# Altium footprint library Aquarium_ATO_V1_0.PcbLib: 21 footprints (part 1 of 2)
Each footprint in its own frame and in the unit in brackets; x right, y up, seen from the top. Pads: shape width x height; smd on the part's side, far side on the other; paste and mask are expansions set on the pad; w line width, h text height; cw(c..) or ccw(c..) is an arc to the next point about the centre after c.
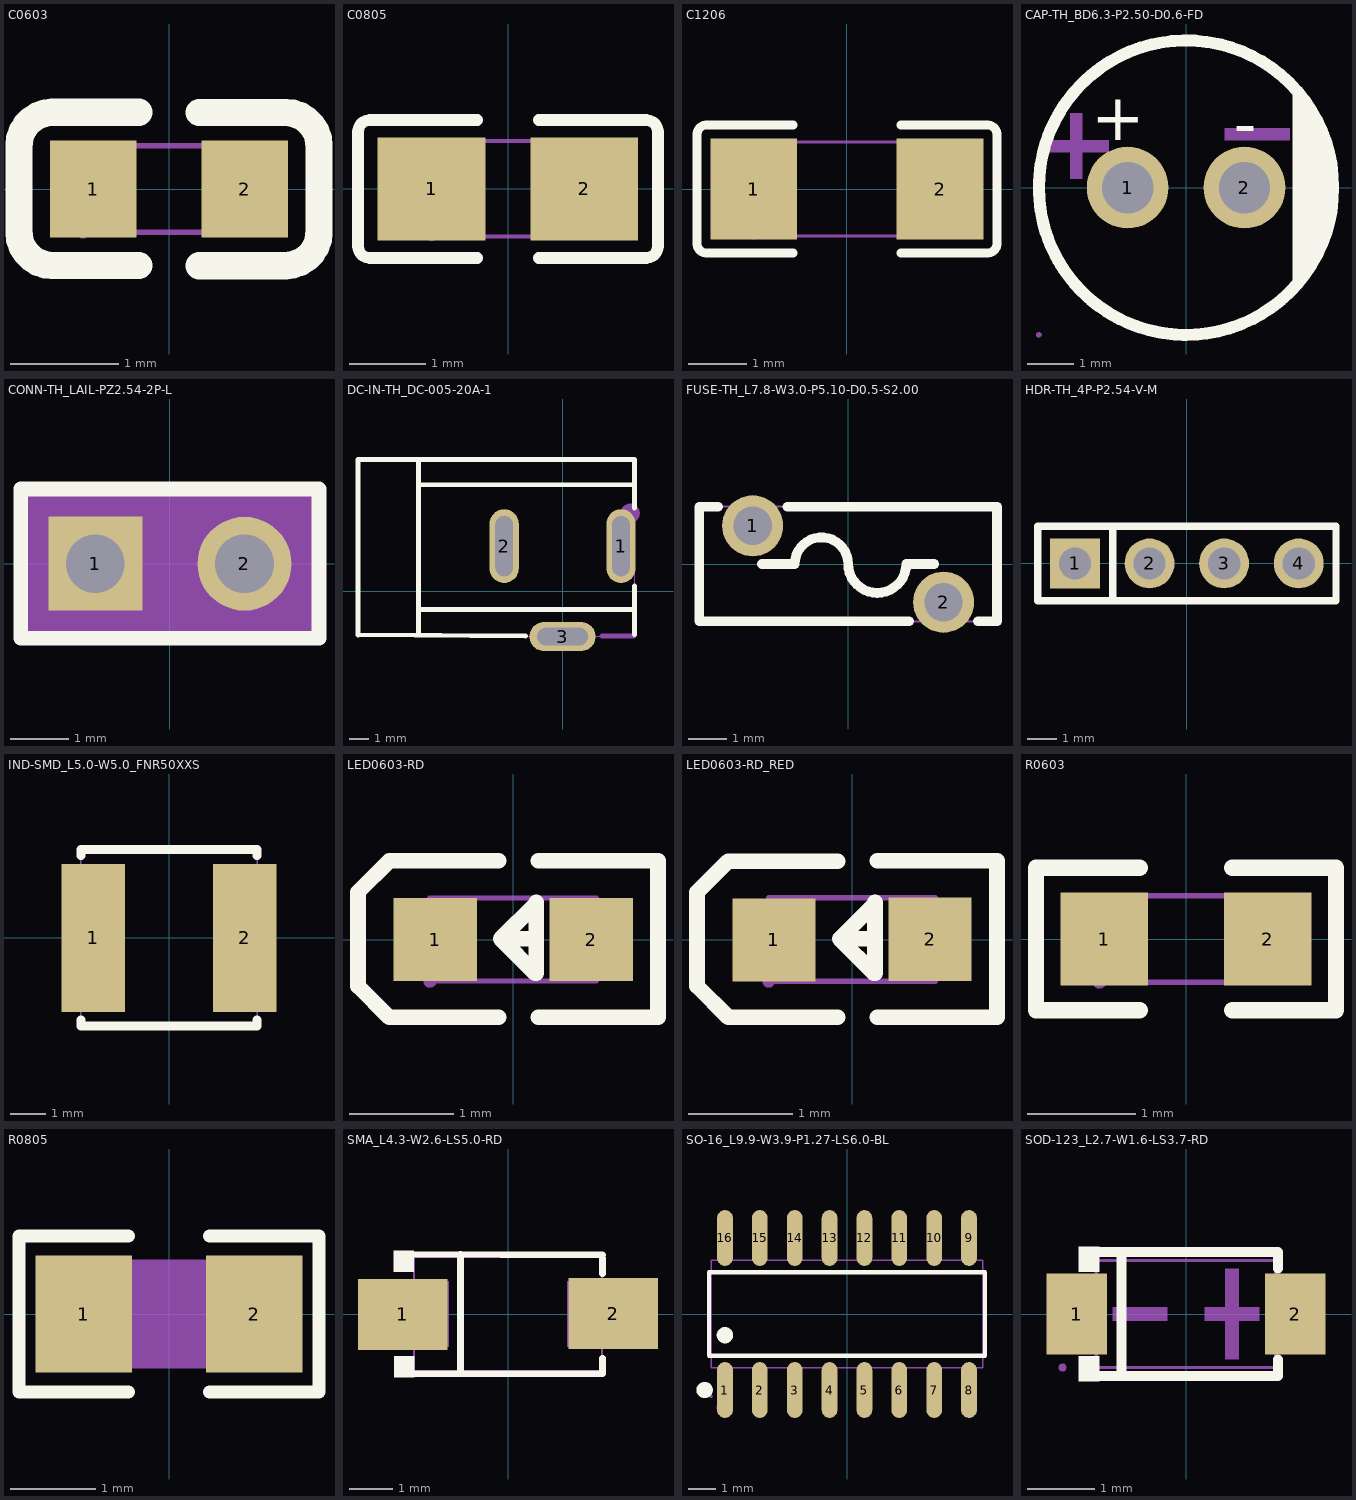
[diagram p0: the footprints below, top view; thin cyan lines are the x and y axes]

## C0603 [mil]
pads (2):
  rect 31.5x35.4 smd: 1(-27.6,0) 2(27.6,0)
Top Overlay:
  lines w10: -11,-27.9 -42.5,-27.9 -45.2,-27.6 -47.8,-26.7 -50.1,-25.3 -52.1,-23.3 -53.5,-21 -54.4,-18.5 -54.7,-15.7 -54.7,15.8 -54.4,18.5 -53.5,21 -52.1,23.4 -50.1,25.3 -47.8,26.7 -45.2,27.7 -42.5,28 -11,28 ; 11,-28 42.5,-28 45.2,-27.6 47.8,-26.7 50.1,-25.3 52.1,-23.4 53.5,-21 54.4,-18.5 54.7,-15.8 54.7,15.7 54.4,18.5 53.5,21 52.1,23.3 50.1,25.3 47.8,26.7 45.2,27.6 42.5,27.9 11,27.9
Mechanical 7:
  lines w2: -31.5,-15.7 31.5,-15.7 31.5,15.7 -31.5,15.7 -31.5,-15.7
Mechanical 8:
  region: -29.1,-15.8 -29.5,-17 -30.5,-17.9 -31.8,-18.1 -33,-17.5 -33.8,-16.4 -33.8,-15.1 -33,-14 -31.8,-13.4 -30.5,-13.6 -29.5,-14.5
Mechanical 9:
  region: 31.5,-15.7 31.5,15.7 19.7,15.7 19.7,-15.7
  region: -31.5,-15.7 -31.5,15.7 -19.7,15.7 -19.7,-15.7

## C0805 [mil]
pads (2):
  rect 55.5x53.1 smd paste-3937 mask+2: 1(-39.4,0) 2(39.3,0)
Top Overlay:
  lines w6: -15.8,-35.6 -71.3,-35.6 -73.2,-35.3 -74.9,-34.5 -76.2,-33.1 -77,-31.5 -77.3,-29.6 -77.3,29.5 -77,31.4 -76.2,33.1 -74.9,34.4 -73.2,35.2 -71.3,35.5 -15.8,35.5 ; 15.8,-35.6 71.3,-35.6 73.1,-35.3 74.8,-34.5 76.1,-33.1 77,-31.5 77.3,-29.6 77.3,29.5 77,31.4 76.1,33.1 74.8,34.4 73.1,35.2 71.3,35.5 15.8,35.5
Top Paste:
  region: -67.2,-25.2 -67.2,25.2 -65.2,27.1 -19.9,27.1 -17.9,25.2 -17.7,9 -35.5,9 -35.5,-8.7 -18.1,-8.7 -17.9,-25.2 -19.9,-27.2 -65.2,-27.2
  region: 67.1,25.2 67.1,-25.2 65.1,-27.2 19.9,-27.2 17.9,-25.2 17.7,-9.1 35.4,-9.1 35.4,8.6 18.1,8.6 17.9,25.2 19.9,27.1 65.1,27.1
Mechanical 7:
  lines w2: -39.4,-24.6 -39.4,24.6 39.3,24.6 39.3,-24.6 -39.4,-24.6
Mechanical 8:
  region: -37,-24.6 -37.4,-25.9 -38.4,-26.8 -39.7,-27 -40.9,-26.4 -41.7,-25.3 -41.7,-24 -40.9,-22.9 -39.7,-22.3 -38.4,-22.5 -37.4,-23.4
Mechanical 9:
  region: -39.4,-24.6 -39.4,24.6 -19.7,24.6 -19.7,-24.6
  region: 39.3,24.6 39.3,-24.6 19.7,-24.6 19.7,24.6

## C1206 [mil]
pads (2):
  rect 58.5x68 smd paste-3937 mask+2: 1(-62.7,0) 2(62.7,0)
Top Overlay:
  lines w6: -36.4,-43 -94.9,-43 -96.7,-42.7 -98.4,-41.9 -99.7,-40.6 -100.6,-38.9 -100.9,-37 -100.9,37 -100.6,38.8 -99.7,40.5 -98.4,41.8 -96.7,42.7 -94.9,43 -36.4,43 ; 36.5,-43 95,-43 96.8,-42.7 98.5,-41.9 99.8,-40.6 100.7,-38.9 101,-37 101,37 100.7,38.8 99.8,40.5 98.5,41.8 96.8,42.7 95,43 36.5,43
Top Paste:
  region: 33.5,-30.1 33.5,-15.5 37.5,-11.6 49.5,-11.6 53.4,-7.6 53.4,7.6 49.5,11.5 37.5,11.5 33.5,15.5 33.5,30.1 37.5,34 88,34 92,30.1 92,-30.1 88,-34 37.5,-34
  region: -33.4,-30.1 -33.4,-15.5 -37.4,-11.6 -49.4,-11.6 -53.3,-7.6 -53.3,7.6 -49.4,11.5 -37.4,11.5 -33.4,15.5 -33.4,30.1 -37.4,34 -87.9,34 -91.9,30.1 -91.9,-30.1 -87.9,-34 -37.4,-34
Mechanical 7:
  lines w2: -62.9,-31.5 -62.9,31.5 63,31.5 63,-31.5 -62.9,-31.5
Mechanical 8:
  region: -60.6,-31.5 -61,-32.8 -62,-33.7 -63.3,-33.9 -64.5,-33.3 -65.2,-32.2 -65.2,-30.9 -64.5,-29.7 -63.3,-29.2 -62,-29.4 -61,-30.2
Mechanical 9:
  region: -62.9,-31.5 -62.9,31.5 -43.3,31.5 -43.3,-31.5
  region: 63,-31.5 63,31.5 43.4,31.5 43.4,-31.5

## CAP-TH_BD6.3-P2.50-D0.6-FD [mil]
pads (2):
  round 68.9 hole 43.3 paste+0 mask+2: 1(-49.2,0) 2(49.2,0)
Top Overlay:
  drawing of 160 lines, arcs and shapes, not listed
  text "-" at 40,35 h39.4
  text "+" at -80,40 h39.4
Mechanical 6:
  region: 32.5,50 87.5,50 87.5,40 32.5,40
  region: -97.5,7.5 -97.5,62.5 -87.5,62.5 -87.5,7.5
  region: -120,40 -65,40 -65,30 -120,30
Mechanical 7:
  lines w2: -0.1,-124.1 0,-124.1 ccw(c0,-0.2) 123.9,-0.2 123.9,0.2 ccw(c0,0.2) 0,124.1 -0.1,124.1 ccw(c-0.1,0.1) -124.1,0.1 -124.1,0 ccw(c-0.1,0) -0.1,-124
Mechanical 8:
  region: -121.7,-124.1 -122.1,-125.3 -123.1,-126.2 -124.4,-126.4 -125.6,-125.8 -126.4,-124.7 -126.4,-123.4 -125.6,-122.3 -124.4,-121.7 -123.1,-121.9 -122.1,-122.8
Mechanical 9:
  region: 61,0 60.7,-2.9 59.6,-5.7 57.8,-8.1 55.5,-10 52.9,-11.2 50,-11.8 47,-11.6 44.2,-10.7 41.7,-9.1 39.7,-6.9 38.2,-4.3 37.5,-1.5 37.5,1.5 38.2,4.3 39.7,6.9 41.7,9.1 44.2,10.7 47,11.6 50,11.8 52.9,11.2 55.5,10 57.8,8.1 59.6,5.7 60.7,2.9
  region: -37.4,0 -37.8,-2.9 -38.9,-5.7 -40.6,-8.1 -42.9,-10 -45.6,-11.2 -48.5,-11.8 -51.4,-11.6 -54.2,-10.7 -56.7,-9.1 -58.8,-6.9 -60.2,-4.3 -60.9,-1.5 -60.9,1.5 -60.2,4.3 -58.8,6.9 -56.7,9.1 -54.2,10.7 -51.4,11.6 -48.5,11.8 -45.6,11.2 -42.9,10 -40.6,8.1 -38.9,5.7 -37.8,2.9

## CONN-TH_LAIL-PZ2.54-2P-L [mil]
pads (2):
  rect 63x63 hole 39.4 paste+0 mask+2: 1(-50,0)
  round 63 hole 39.4 paste+0 mask+2: 2(50,0)
Top Overlay:
  lines w10: -100,-50 100,-50 100,50 -100,50 -100,-50
Mechanical 7:
  region: -100,-49.2 -100,49.2 100,49.2 100,-49.2
Mechanical 8:
  region: -98.8,-49.2 -99.2,-50 -100,-50.4 -100.8,-50 -101.2,-49.2 -100.8,-48.4 -100,-48 -99.2,-48.4
Mechanical 9:
  region: 37.4,12.6 62.6,12.6 62.6,-12.6 37.4,-12.6
  region: -62.6,12.6 -37.4,12.6 -37.4,-12.6 -62.6,-12.6

## DC-IN-TH_DC-005-20A-1 [mil]
pads (3):
  oval 59.1x149.6 hole 35.4 slot 122.1 at 90 deg: 1(118.2,91.5) 2(-118.1,91.5)
  oval 133.9x59.1 hole 35.4 slot 102.4 at 0 deg: 3(0,-91.5)
Top Overlay:
  lines w10: -413.9,-87.9 -413.9,266.4 ; -413.8,-87.8 -75,-90 ; -413.8,266.7 145.9,266.6 ; -291.3,-87.6 -291.3,266.8 ; -288.2,-36.4 145.5,-36.4 ; -288.2,215.6 145.8,215.5 ; 145.7,-87.6 145.7,11.1 ; 145.7,168.1 145.7,266.8
Mechanical 6:
  lines w10: 80,-90 145,-90
  lines w19.7: 126.8,156.5 126.8,159.2 127.5,161.8 128.9,164.1 130.9,165.9 133.3,167.1 135.9,167.7 138.6,167.5 141.1,166.6 143.3,165 145,163 146.1,160.5 146.4,157.9 146.1,155.2 145,152.7 143.3,150.7 141.1,149.1 138.6,148.2 135.9,148 133.3,148.6 130.9,149.8 128.9,151.6 127.5,153.9 126.8,156.5
Mechanical 7:
  lines w2: -413.4,-90.6 145.7,-90.6 145.7,266.8 -413.4,266.8 -413.4,-90.6
Mechanical 8:
  region: 148,266.8 147.7,265.5 146.7,264.6 145.3,264.4 144.1,265 143.4,266.1 143.4,267.4 144.1,268.5 145.3,269.1 146.7,268.9 147.7,268
Mechanical 9:
  region: -49.2,-97.4 -49.2,-85.6 49.2,-85.6 49.2,-97.4
  region: -113.2,42.3 -123,42.3 -123,140.7 -113.2,140.7
  region: 112.2,140.7 124,140.7 124,42.3 112.2,42.3

## FUSE-TH_L7.8-W3.0-P5.10-D0.5-S2.00 [mil]
pads (2):
  round 63 hole 39.4: 1(-98.4,39.4) 2(98.4,-39.4)
Top Overlay:
  lines w10: -133.9,59.1 -153.5,59.1 -153.5,-59 62.9,-59 ; -88.8,0 -55,0 -54.6,4.5 -53.5,8.9 -51.7,13.1 -49.2,16.9 -46.1,20.2 -42.5,23 -38.5,25.2 -34.3,26.7 -29.8,27.4 -25.2,27.4 -20.7,26.7 -16.5,25.2 -12.5,23 -8.9,20.2 -5.8,16.9 -3.3,13.1 -1.5,8.9 -0.4,4.5 0,0 0.4,-4.7 1.5,-9.2 3.3,-13.5 5.8,-17.5 8.9,-21.1 12.4,-24.1 16.4,-26.6 20.8,-28.3 25.3,-29.4 30,-29.8 34.7,-29.4 39.2,-28.3 43.6,-26.6 47.6,-24.1 51.2,-21.1 54.2,-17.5 56.7,-13.5 58.5,-9.2 59.6,-4.7 60,0 88.8,0 ; -62.9,59.1 153.5,59.1 153.5,-59 133.9,-59
Mechanical 7:
  lines w2: -153.5,-59.1 153.5,-59.1 153.5,59.1 -153.5,59.1 -153.5,-59.1
Mechanical 8:
  region: -151.2,59.1 -151.6,57.8 -152.6,56.9 -153.9,56.7 -155.1,57.3 -155.8,58.4 -155.8,59.7 -155.1,60.8 -153.9,61.4 -152.6,61.2 -151.6,60.3
Mechanical 9:
  region: 114.2,-39.4 113.8,-42.9 112.6,-46.2 110.7,-49.2 108.2,-51.7 105.3,-53.6 101.9,-54.7 98.4,-55.1 94.9,-54.7 91.6,-53.6 88.6,-51.7 86.1,-49.2 84.2,-46.2 83.1,-42.9 82.7,-39.4 83.1,-35.9 84.2,-32.5 86.1,-29.6 88.6,-27.1 91.6,-25.2 94.9,-24 98.4,-23.6 101.9,-24 105.3,-25.2 108.2,-27.1 110.7,-29.6 112.6,-32.5 113.8,-35.9
  region: -82.7,39.4 -83.1,35.9 -84.2,32.5 -86.1,29.6 -88.6,27.1 -91.6,25.2 -94.9,24 -98.4,23.6 -101.9,24 -105.3,25.2 -108.2,27.1 -110.7,29.6 -112.6,32.5 -113.8,35.9 -114.2,39.4 -113.8,42.9 -112.6,46.2 -110.7,49.2 -108.2,51.7 -105.3,53.6 -101.9,54.7 -98.4,55.1 -94.9,54.7 -91.6,53.6 -88.6,51.7 -86.1,49.2 -84.2,46.2 -83.1,42.9

## HDR-TH_4P-P2.54-V-M [mil]
pads (4):
  rect 66.9x66.9 hole 43.3: 1(-150,0)
  round 66.9 hole 43.3: 2(-50,0) 3(50,0) 4(150,0)
Top Overlay:
  lines w10: -99.1,-50 -99.1,50 ; -99.1,50 200,50 200,-50 -200,-50 -200,50 -99.1,50
Mechanical 7:
  lines w2: -200,-49.2 -200,49.2 200,49.2 200,-49.2 -200,-49.2
Mechanical 8:
  region: -197.6,-49.2 -198,-50.5 -199,-51.4 -200.3,-51.5 -201.5,-51 -202.3,-49.9 -202.3,-48.5 -201.5,-47.4 -200.3,-46.9 -199,-47.1 -198,-47.9
Mechanical 9:
  region: -162.6,12.6 -137.4,12.6 -137.4,-12.6 -162.6,-12.6
  region: -62.6,12.6 -37.4,12.6 -37.4,-12.6 -62.6,-12.6
  region: 37.4,12.6 62.6,12.6 62.6,-12.6 37.4,-12.6
  region: 137.4,12.6 162.6,12.6 162.6,-12.6 137.4,-12.6

## IND-SMD_L5.0-W5.0_FNR50XXS [mil]
pads (2):
  rect 70.9x165.4 smd: 1(-84.6,0) 2(84.6,0)
Top Overlay:
  lines w10: -98.4,-91.8 -98.4,-98.4 98.4,-98.4 98.4,-91.8 ; -98.4,91.8 -98.4,98.4 98.4,98.4 98.4,91.8
Mechanical 7:
  lines w2: -98.4,-98.4 98.4,-98.4 98.4,98.4 -98.4,98.4 -98.4,-98.4
Mechanical 8:
  region: -96.1,-98.4 -96.4,-99.7 -97.4,-100.6 -98.8,-100.8 -100,-100.2 -100.7,-99.1 -100.7,-97.8 -100,-96.6 -98.8,-96.1 -97.4,-96.3 -96.4,-97.2
Mechanical 9:
  region: -98.4,78.7 -49.2,78.7 -49.2,-78.7 -98.4,-78.7
  region: 98.4,-78.7 49.2,-78.7 49.2,78.7 98.4,78.7

## LED0603-RD [mil]
pads (2):
  rect 31.5x31.5 smd: 1(-29.5,0) 2(29.5,0)
Top Overlay:
  lines w5.9: -5.5,-29.4 -46.8,-29.4 -58.6,-17.6 -58.6,-13.6 -58.6,13.9 -58.6,17.9 -46.8,29.7 -5.5,29.7 ; 8.7,0.3 -4.7,0.3 ; 9.5,-29.3 54.7,-29.3 ; 9.5,29.8 54.7,29.8 54.7,-28.5 ; -4.7,0.3 8.3,-12.7 8.7,-12.7 8.7,14 8.7,13.6 -4.7,0.3
Mechanical 6:
  region: -42.1,2.4 -20.9,2.4 -20.9,-2.7 -42.1,-2.7
  region: 28.9,-10.5 28.9,10.7 34,10.7 34,-10.5
  region: 20.8,2.7 42.1,2.7 42.1,-2.4 20.8,-2.4
Mechanical 7:
  lines w2: -31.5,-15.7 -31.5,15.7 31.5,15.7 31.5,-15.7 -31.5,-15.7
Mechanical 8:
  region: -29.1,-15.9 -29.5,-17.2 -30.5,-18 -31.8,-18.2 -33,-17.7 -33.7,-16.6 -33.7,-15.2 -33,-14.1 -31.8,-13.5 -30.5,-13.7 -29.5,-14.6
Mechanical 9:
  region: -31.5,-15.9 -31.5,15.6 -19.7,15.6 -19.7,-15.9
  region: 19.7,-15.6 19.7,15.9 31.5,15.9 31.5,-15.6

## LED0603-RD_RED [mil]
pads (2):
  rect 31.5x31.5 smd: 1(-29.5,-0.1) 2(29.5,0.2)
Top Overlay:
  lines w5.9: -5.5,-29.3 -46.8,-29.3 -58.6,-17.5 -58.6,-13.6 -58.6,14 -58.6,17.9 -46.8,29.7 -5.5,29.7 ; 8.7,0.3 -4.7,0.3 ; 9.5,-29.3 54.8,-29.3 ; 9.5,29.8 54.8,29.8 54.8,-28.5 ; -4.7,0.3 8.3,-12.7 8.7,-12.7 8.7,14.1 8.7,13.7 -4.7,0.3
Mechanical 6:
  region: 20.8,2.7 42.1,2.7 42.1,-2.4 20.8,-2.4
  region: 28.9,-10.5 28.9,10.8 34.1,10.8 34.1,-10.5
  region: -42.1,2.4 -20.8,2.4 -20.8,-2.7 -42.1,-2.7
Mechanical 7:
  lines w2: -31.5,-15.7 -31.5,15.8 31.5,15.8 31.5,-15.7 -31.5,-15.7
Mechanical 8:
  region: -29.1,-15.9 -29.5,-17.1 -30.5,-18 -31.8,-18.2 -33,-17.6 -33.7,-16.5 -33.7,-15.2 -33,-14.1 -31.8,-13.5 -30.5,-13.7 -29.5,-14.6
Mechanical 9:
  region: 19.7,-15.6 19.7,15.9 31.5,15.9 31.5,-15.6
  region: -31.5,-15.9 -31.5,15.6 -19.6,15.6 -19.6,-15.9

## R0603 [mil]
pads (2):
  rect 31.8x34 smd paste-3937 mask+2: 1(-29.7,0) 2(29.6,0)
Top Overlay:
  lines w6: -16.8,-26 -54.6,-26 -54.6,26 -16.8,26 ; 16.7,-26 54.5,-26 54.5,26 16.7,26
Top Paste:
  region: 47,17.7 15.5,17.7 13.6,15.7 13.6,6.8 28.1,6.8 28.1,-6.2 13.6,-6.2 13.6,-15.8 15.5,-17.7 47,-17.7 49,-15.8 49,15.7
  region: -47.1,-17.7 -15.6,-17.7 -13.6,-15.8 -13.6,-6.8 -28.2,-6.8 -28.2,6.2 -13.6,6.2 -13.6,15.7 -15.6,17.7 -47.1,17.7 -49,15.7 -49,-15.8
Mechanical 7:
  lines w2: -31.5,-15.8 -31.5,15.7 31.5,15.7 31.5,-15.8 -31.5,-15.8
Mechanical 8:
  region: -29.2,-15.8 -29.5,-17 -30.6,-17.9 -31.9,-18.1 -33.1,-17.5 -33.8,-16.4 -33.8,-15.1 -33.1,-14 -31.9,-13.4 -30.6,-13.6 -29.5,-14.5
Mechanical 9:
  region: -31.5,-15.8 -31.5,15.7 -19.7,15.7 -19.7,-15.8
  region: 31.5,-15.8 31.5,15.7 19.7,15.7 19.7,-15.8

## R0805 [mil]
pads (2):
  rect 44.6x54.2 smd paste-3937 mask+2: 1(-39.4,0) 2(39.4,0)
Top Overlay:
  lines w6: -18.7,-36.1 -69.3,-36.1 -69.3,36.1 -18.7,36.1 ; 18.7,-36.1 69.3,-36.1 69.3,36.1 18.7,36.1
Top Paste:
  region: -66.9,-25.2 -66.9,25.2 -65,27.2 -19.7,27.2 -17.7,25.2 -17.5,9.1 -35.2,9.1 -35.2,-8.7 -17.9,-8.7 -17.7,-25.2 -19.7,-27.2 -65,-27.2
  region: 17.7,-25.2 17.7,-8.7 35.2,-8.7 35.2,9.1 17.9,9.1 17.7,25.2 19.7,27.2 65,27.2 66.9,25.2 66.9,-25.2 65,-27.2 19.7,-27.2
Mechanical 7:
  region: -39.4,-25.1 -39.4,25.1 39.4,25.1 39.4,-25.1
Mechanical 8:
  region: -38.2,-25.1 -38.5,-25.9 -39.4,-26.3 -40.2,-25.9 -40.5,-25.1 -40.2,-24.3 -39.4,-23.9 -38.5,-24.3
Mechanical 9:
  region: -39.4,-25.1 -39.4,25.1 -23.6,25.1 -23.6,-25.1
  region: 39.4,-25.1 39.4,25.1 23.6,25.1 23.6,-25.1

## SMA_L4.3-W2.6-LS5.0-RD [mil]
pads (2):
  rect 80.6x63.8 smd: 1(-94.6,-0.4) 2(94.6,0.4)
Top Overlay:
  region: -84.9,56.7 -84.9,37.9 -102.9,37.9 -102.9,56.7
  region: -84.4,-56.7 -84.4,-37.9 -102.4,-37.9 -102.4,-56.7
  lines w6: -99.4,53.7 85,53 ; -98.6,-53.7 85.2,-53.7 ; -42.7,-53.7 -42.7,53.7 ; 85,-53.7 85,-39.9 ; 85,36.2 85,50
Mechanical 6:
  region: -95.7,-3.8 -95.7,3.8 -65.3,3.8 -65.3,-3.8
  region: 95.7,-3.8 95.7,3.8 65.3,3.8 65.3,-3.8
  region: 84.3,-25.3 84.3,25.3 76.7,25.3 76.7,-25.3
Mechanical 7:
  lines w2: -84.6,-51.2 -84.6,51.2 84.6,51.2 84.6,-51.2 -84.6,-51.2
Mechanical 8:
  region: -96.1,-51.2 -96.4,-52.5 -97.4,-53.3 -98.8,-53.5 -100,-53 -100.7,-51.8 -100.7,-50.5 -100,-49.4 -98.8,-48.8 -97.4,-49 -96.4,-49.9
Mechanical 9:
  region: 98.4,-29.5 98.4,29.5 53.5,29.5 53.5,-29.5
  region: -98.4,29.5 -98.4,-29.5 -53.5,-29.5 -53.5,29.5

## SO-16_L9.9-W3.9-P1.27-LS6.0-BL [mil]
pads (16):
  oval 22.6x80.2 smd: 1(-175,-109) 2(-125,-109) 3(-75,-109) 4(-25,-109) 5(25,-109) 6(75,-109) 7(125,-109) 8(175,-109) 9(175,109) 10(125,109) 11(75,109) 12(25,109) 13(-25,109) 14(-75,109) 15(-125,109) 16(-175,109)
Top Overlay:
  lines w6: -197.9,-59.9 -197.9,59.9 197.9,59.9 197.9,-59.9 -197.9,-59.9
  lines w11.8: -210,-109 -209.7,-111 -208.6,-112.8 -207.1,-114.1 -205.1,-114.8 -203.1,-114.8 -201.2,-114.1 -199.6,-112.8 -198.6,-111 -198.2,-109 -198.6,-107 -199.6,-105.2 -201.2,-103.9 -203.1,-103.2 -205.1,-103.2 -207.1,-103.9 -208.6,-105.2 -209.7,-107 -210,-109 ; -180.9,-30.3 -180.6,-32.3 -179.5,-34.1 -178,-35.4 -176,-36.1 -174,-36.1 -172,-35.4 -170.5,-34.1 -169.4,-32.3 -169.1,-30.3 -169.4,-28.3 -170.5,-26.5 -172,-25.2 -174,-24.5 -176,-24.5 -178,-25.2 -179.5,-26.5 -180.6,-28.3 -180.9,-30.3
Mechanical 6:
  lines w11.8: -180.9,-133.9 -180.6,-135.9 -179.5,-137.7 -178,-139 -176,-139.7 -174,-139.7 -172,-139 -170.5,-137.7 -169.4,-135.9 -169.1,-133.9 -169.4,-131.8 -170.5,-130.1 -172,-128.7 -174,-128 -176,-128 -178,-128.7 -179.5,-130.1 -180.6,-131.8 -180.9,-133.9
Mechanical 7:
  lines w2: -194.9,-76.8 -194.9,76.8 194.9,76.8 194.9,-76.8 -194.9,-76.8
Mechanical 8:
  region: -192.5,-118.1 -192.9,-119.4 -193.9,-120.3 -195.2,-120.4 -196.4,-119.9 -197.1,-118.8 -197.1,-117.4 -196.4,-116.3 -195.2,-115.8 -193.9,-116 -192.9,-116.8
Mechanical 9:
  region: -183.5,-118.1 -183.5,-92.5 -166.5,-92.5 -166.5,-118.1
  region: -133.5,-118.1 -133.5,-92.5 -116.5,-92.5 -116.5,-118.1
  region: -83.5,-118.1 -83.5,-92.5 -66.5,-92.5 -66.5,-118.1
  region: -33.5,-118.1 -33.5,-92.5 -16.5,-92.5 -16.5,-118.1
  region: 16.5,-118.1 16.5,-92.5 33.5,-92.5 33.5,-118.1
  region: 66.5,-118.1 66.5,-92.5 83.5,-92.5 83.5,-118.1
  region: 116.5,-118.1 116.5,-92.5 133.5,-92.5 133.5,-118.1
  region: 166.5,-118.1 166.5,-92.5 183.5,-92.5 183.5,-118.1
  region: -183.5,92.5 -183.5,118.1 -166.5,118.1 -166.5,92.5
  region: -133.5,92.5 -133.5,118.1 -116.5,118.1 -116.5,92.5
  region: -83.5,92.5 -83.5,118.1 -66.5,118.1 -66.5,92.5
  region: -33.5,92.5 -33.5,118.1 -16.5,118.1 -16.5,92.5
  region: 16.5,92.5 16.5,118.1 33.5,118.1 33.5,92.5
  region: 66.5,92.5 66.5,118.1 83.5,118.1 83.5,92.5
  region: 116.5,92.5 116.5,118.1 133.5,118.1 133.5,92.5
  region: 166.5,92.5 166.5,118.1 183.5,118.1 183.5,92.5
Mechanical 10:
  region: -183.5,-92.9 -183.5,-76.4 -166.5,-76.4 -166.5,-92.9
  region: -133.5,-92.9 -133.5,-76.4 -116.5,-76.4 -116.5,-92.9
  region: -83.5,-92.9 -83.5,-76.4 -66.5,-76.4 -66.5,-92.9
  region: -33.5,-92.9 -33.5,-76.4 -16.5,-76.4 -16.5,-92.9
  region: 16.5,-92.9 16.5,-76.4 33.5,-76.4 33.5,-92.9
  region: 66.5,-92.9 66.5,-76.4 83.5,-76.4 83.5,-92.9
  region: 116.5,-92.9 116.5,-76.4 133.5,-76.4 133.5,-92.9
  region: 166.5,-92.9 166.5,-76.4 183.5,-76.4 183.5,-92.9
  region: -183.5,76.4 -183.5,92.9 -166.5,92.9 -166.5,76.4
  region: -133.5,76.4 -133.5,92.9 -116.5,92.9 -116.5,76.4
  region: -83.5,76.4 -83.5,92.9 -66.5,92.9 -66.5,76.4
  region: -33.5,76.4 -33.5,92.9 -16.5,92.9 -16.5,76.4
  region: 16.5,76.4 16.5,92.9 33.5,92.9 33.5,76.4
  region: 66.5,76.4 66.5,92.9 83.5,92.9 83.5,76.4
  region: 116.5,76.4 116.5,92.9 133.5,92.9 133.5,76.4
  region: 166.5,76.4 166.5,92.9 183.5,92.9 183.5,76.4

## SOD-123_L2.7-W1.6-LS3.7-RD [mil]
pads (2):
  rect 35.8x48 smd: 1(-64.4,0) 2(64.4,0)
Top Overlay:
  region: -51.2,-39.5 -51.2,-24.9 -63.2,-24.9 -63.2,-39.5
  region: -51.2,39.5 -51.2,24.9 -63.2,24.9 -63.2,39.5
  lines w6: -54.2,-36.5 54.2,-36.5 54.2,-26.9 ; -54.2,36.5 54.2,36.5 54.2,26.9 ; -38.1,-36.5 -38.1,36.5
Mechanical 6:
  region: 31.1,26.8 31.1,-26.8 23.1,-26.8 23.1,26.8
  region: 43.2,4 43.2,-4 11,-4 11,4
  region: -43.2,4 -43.2,-4 -11,-4 -11,4
Mechanical 7:
  lines w2: -53,-31.5 53,-31.5 53,31.5 -53,31.5 -53,-31.5
Mechanical 8:
  region: -70.5,-31.5 -70.8,-32.8 -71.8,-33.6 -73.2,-33.8 -74.4,-33.3 -75.1,-32.2 -75.1,-30.8 -74.4,-29.7 -73.2,-29.2 -71.8,-29.4 -70.8,-30.2
Mechanical 9:
  region: 62.8,11.8 72.6,11.8 72.6,-11.8 62.8,-11.8
  region: -72.6,11.8 -62.8,11.8 -62.8,-11.8 -72.6,-11.8
Mechanical 10:
  region: -71.3,-11.8 -52.4,-11.8 -52.4,11.8 -71.3,11.8
  region: 71.3,11.8 52.4,11.8 52.4,-11.8 71.3,-11.8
